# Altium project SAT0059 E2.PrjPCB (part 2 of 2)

## Sheet MCU.SchDoc: MCU
size 431 x 279 mm; Date: Not shown in title block; ApprovedBy: Not shown in title block; CheckedBy: Not shown in title block; Author: Not shown in title block; CompanyName: Not shown in title block; DrawnBy: B. Shaffer; Engineer: Not shown in title block; Organization: Not shown in title block; Address1: Not shown in title block; Address2: Not shown in title block; Address3: Not shown in title block; Address4: Not shown in title block; DocumentNumber: 6; Revision: Use project parameter SCH_Rev; SheetNumber: 6; SheetTotal: 8; PageSetup: Record=PageOptions|CenterHorizontal=True|CenterVertical=True|PrintScale=0.96|XCorrection=1.00|YCorrection=1.00|PrintKind=0|BorderSize=5000000|LeftOffset=0|BottomOffset=0|Orientation=2|PaperLength=1000|PaperWidth=1000|Scale=100|PaperSource=15|PrintQuality=600|MediaType=1|DitherType=10|PaperKind=11x17|PrintScaleMode=1
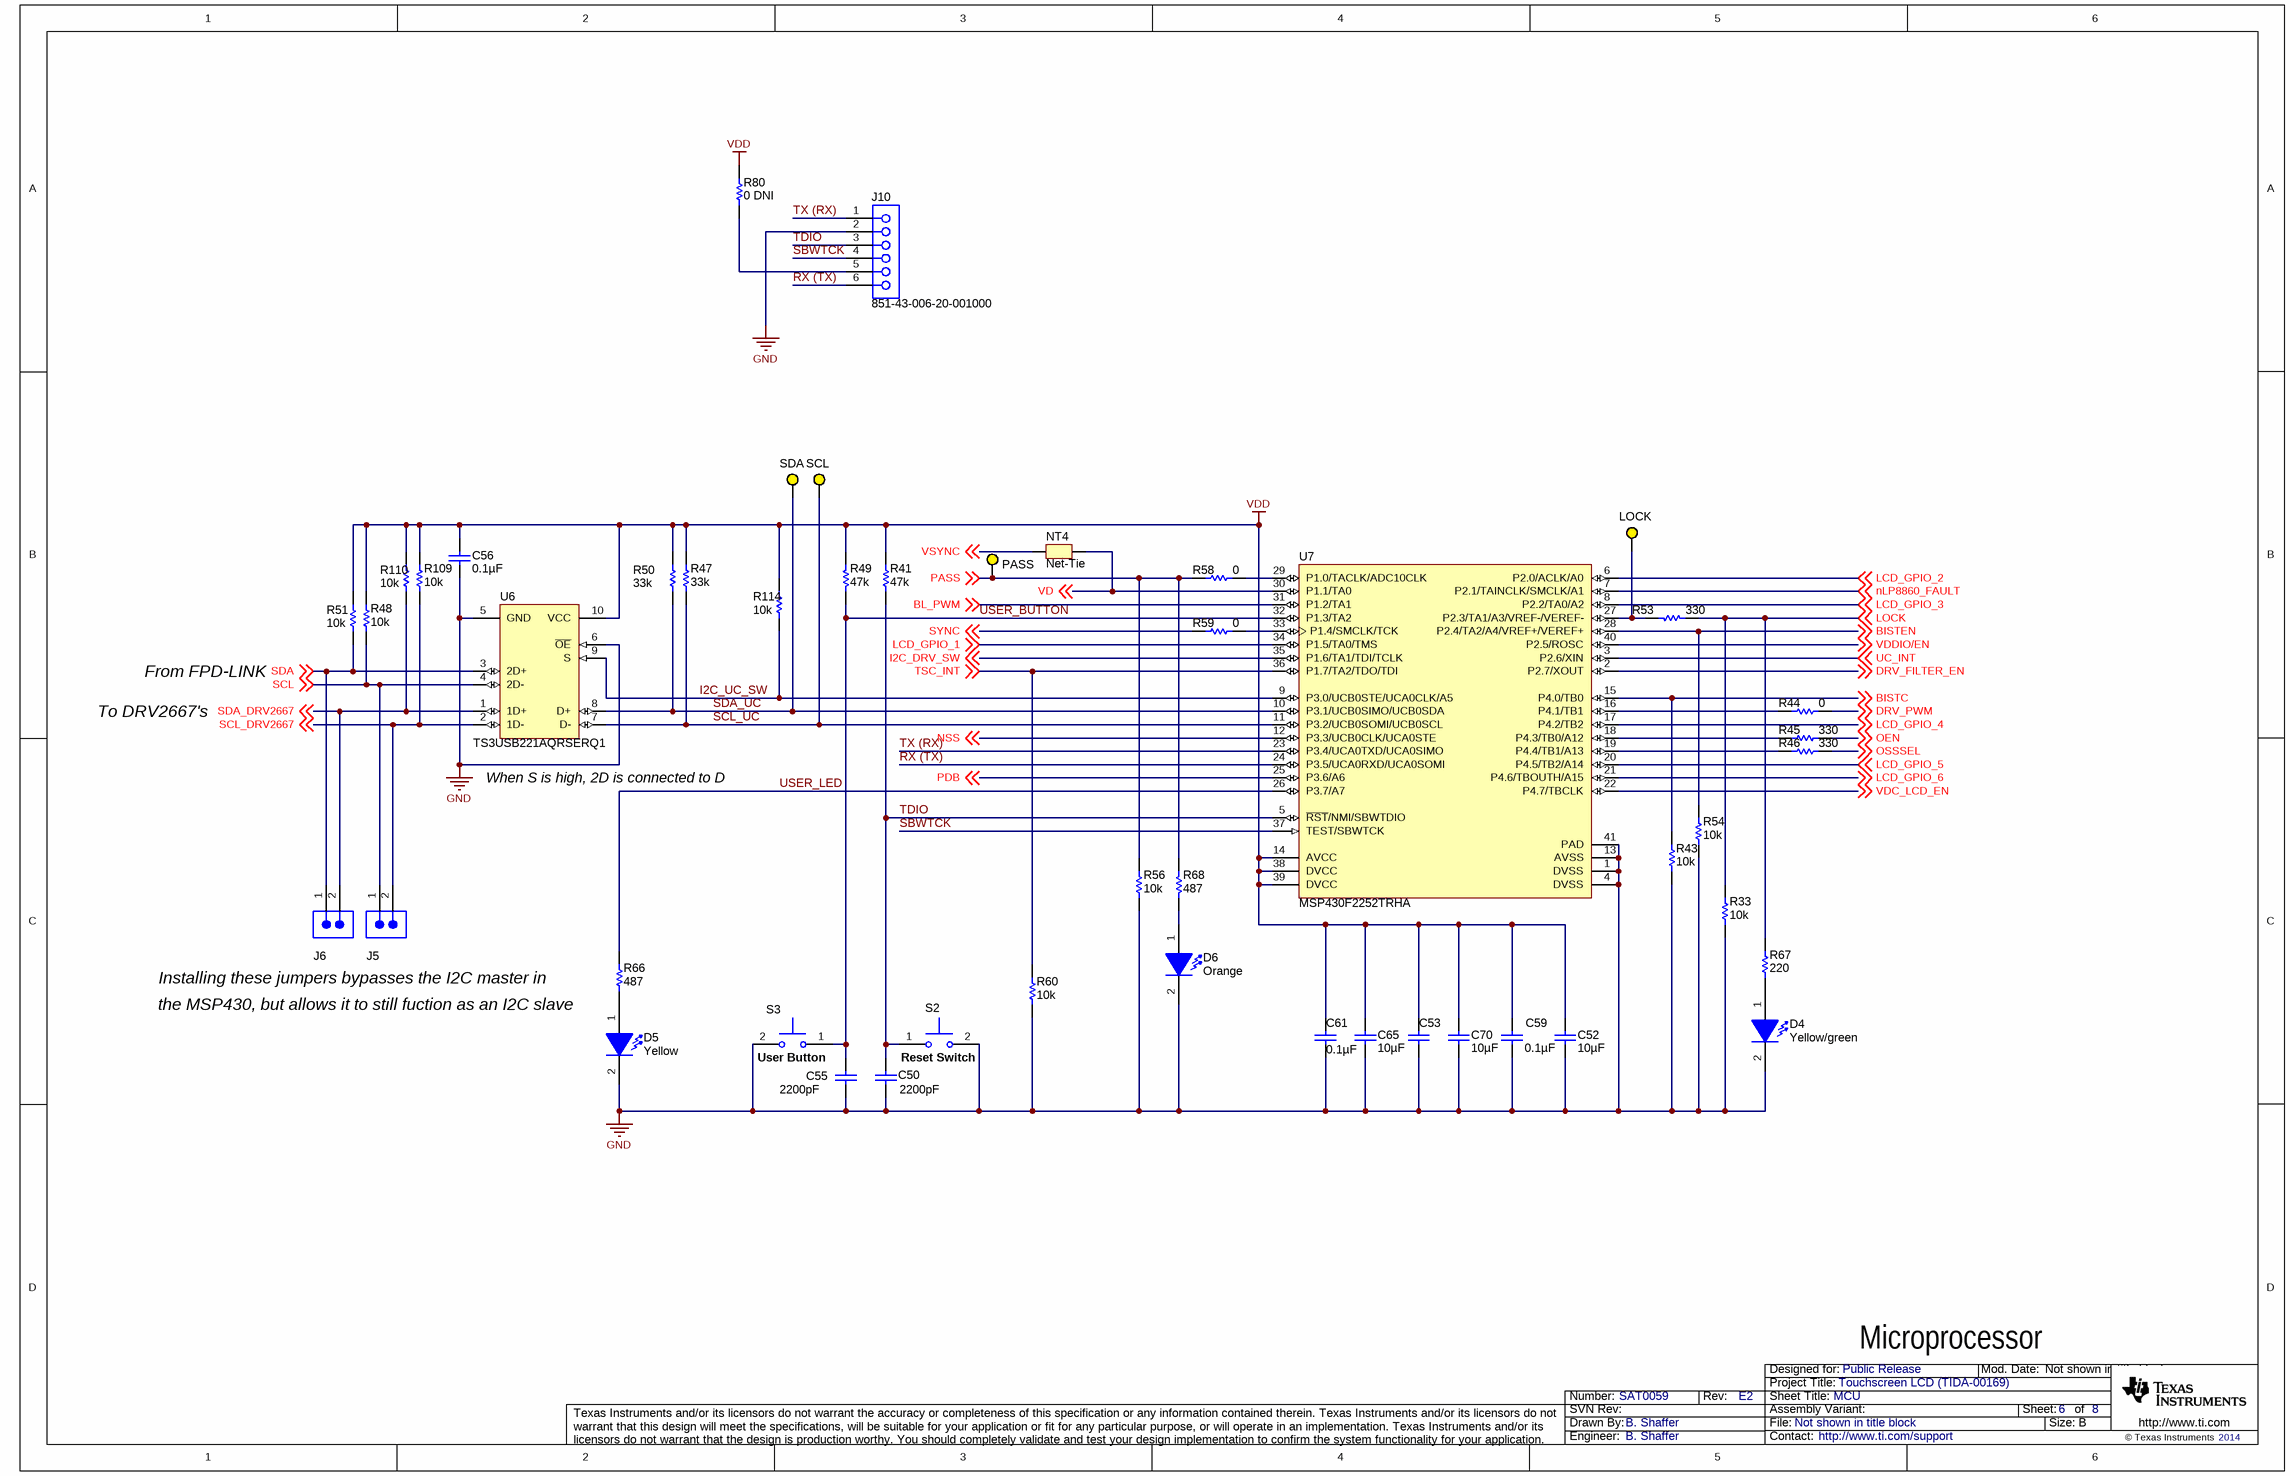
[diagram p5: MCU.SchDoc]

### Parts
C50  value 2200pF  [0402]  (hidden comment: UMK105B7222KV-F)
C52  ValueDisplayed: 10µF  [0805_HV]  (hidden comment: GRM21BR71A106KE51L)
C53  C1005X5R1A104K  [0402]  (value not drawn)
C55  value 2200pF  [0402]  (hidden comment: UMK105B7222KV-F)
C56  ValueDisplayed: 0.1µF  [0603]  (hidden comment: 0603YC104JAT2A)
C59  ValueDisplayed: 0.1µF  [0402]  (hidden comment: C1005X5R1A104K)
C61  ValueDisplayed: 0.1µF  [0402]  (hidden comment: C1005X5R1A104K)
C65  ValueDisplayed: 10µF  [0805_HV]  (hidden comment: GRM21BR71A106KE51L)
C70  ValueDisplayed: 10µF  [0805_HV]  (hidden comment: GRM21BR71A106KE51L)
D4  value Yellow/green  [SML-P1_YELLOW-GREEN]  (hidden comment: SML-P12MTT86)
D5  value Yellow  [LED_SMLP12_Yellow]  (hidden comment: SML-P12YTT86)
D6  value Orange  [LED_SMLP12_ORANGE]  (hidden comment: SML-P12DTT86)
J5  TSW-102-07-G-S  [TSW-102-07-G-S]  (value not drawn)
J6  TSW-102-07-G-S  [TSW-102-07-G-S]  (value not drawn)
J10  851-43-006-20-001000  [CONN_851-43-006-20-001000]
LOCK  5004  [Keystone5004]  (value not drawn)
NT4  Net-Tie  [Net-Tie_10mil]  (net tie, no BOM)
PASS  5004  [Keystone5004]  (value not drawn)
R33  value 10k  [0402]  (hidden comment: CRCW040210K0JNED)
R41  value 47k  [0402]  (hidden comment: CRCW040247K0JNED)
R43  value 10k  [0402]  (hidden comment: CRCW040210K0JNED)
R44  value 0  [0603]  (hidden comment: CRCW06030000Z0EA)
R45  value 330  [0402]  (hidden comment: CRCW0402330RJNED)
R46  value 330  [0402]  (hidden comment: CRCW0402330RJNED)
R47  value 33k  [0402]  (hidden comment: CRCW040233K0JNED)
R48  value 10k  [0402]  (hidden comment: CRCW040210K0JNED)
R49  value 47k  [0402]  (hidden comment: CRCW040247K0JNED)
R50  value 33k  [0402]  (hidden comment: CRCW040233K0JNED)
R51  value 10k  [0402]  (hidden comment: CRCW040210K0JNED)
R53  value 330  [0402]  (hidden comment: CRCW0402330RJNED)
R54  value 10k  [0402]  (hidden comment: CRCW040210K0JNED)
R56  value 10k  [0402]  (hidden comment: CRCW040210K0JNED)
R58  value 0  [0603]  (hidden comment: CRCW06030000Z0EA)
R59  value 0  [0603]  (hidden comment: CRCW06030000Z0EA)
R60  value 10k  [0402]  (hidden comment: CRCW040210K0JNED)
R66  value 487  [0402]  (hidden comment: CRCW0402487RFKED)
R67  value 220  [0402]  (hidden comment: CRCW0402220RJNED)
R68  value 487  [0402]  (hidden comment: CRCW0402487RFKED)
R80  value 0 DNI  [0603]  (hidden comment: CRCW06030000Z0EA)
R109  value 10k  [0402]  (hidden comment: CRCW040210K0JNED)
R110  value 10k  [0402]  (hidden comment: CRCW040210K0JNED)
R114  value 10k  [0603]  (hidden comment: CRCW060310K0JNEA)
S2  SKRKAEE010  [SW_SKRKAEE010]  (value not drawn)
S3  SKRKAEE010  [SW_SKRKAEE010]  (value not drawn)
SCL  5004  [Keystone5004]  (value not drawn)
SDA  5004  [Keystone5004]  (value not drawn)
U6  TS3USB221AQRSERQ1  [RSE0010A]
U7  MSP430F2252TRHA  [RHA0040B]

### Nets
GND: C50.2 C52.2 C53.2 C55.2 C56.2 C59.2 C61.2 C65.2 C70.2 D4.2(K) D5.2(K) D6.2(K) J10.2 R33.1 R43.1 R54.1 R56.1 R60.1 S2.2 S3.2 U6.5(GND) U6.6(~{OE}) U7.1(DVSS) U7.4(DVSS) U7.13(AVSS) U7.41(PAD)
VDD: C52.1 C53.1 C56.1 C59.1 C61.1 C65.1 C70.1 R41.2 R47.2 R48.2 R49.2 R50.2 R51.2 R80.2 R109.2 R110.2 R114.1 U6.10(VCC) U7.14(AVCC) U7.38(DVCC) U7.39(DVCC)
BISTC: R43.2 U7.15(P4.0/TB0) ; off-sheet BISTC
BISTEN: R54.2 U7.28(P2.4/TA2/A4/VREF+/VEREF+) ; off-sheet BISTEN
BL_PWM: U7.31(P1.2/TA1) ; off-sheet BL_PWM
DRV_FILTER_EN: U7.2(P2.7/XOUT) ; off-sheet DRV_FILTER_EN
DRV_PWM: R44.1 ; off-sheet DRV_PWM
I2C_DRV_SW: U7.35(P1.6/TA1/TDI/TCLK) ; off-sheet I2C_DRV_SW
I2C_UC_SW: R114.2 U6.9(S) U7.9(P3.0/UCB0STE/UCA0CLK/A5)
LCD_GPIO_1: U7.34(P1.5/TA0/TMS) ; off-sheet LCD_GPIO_1
LCD_GPIO_2: U7.6(P2.0/ACLK/A0) ; off-sheet LCD_GPIO_2
LCD_GPIO_3: U7.8(P2.2/TA0/A2) ; off-sheet LCD_GPIO_3
LCD_GPIO_4: U7.17(P4.2/TB2) ; off-sheet LCD_GPIO_4
LCD_GPIO_5: U7.20(P4.5/TB2/A14) ; off-sheet LCD_GPIO_5
LCD_GPIO_6: U7.21(P4.6/TBOUTH/A15) ; off-sheet LCD_GPIO_6
LOCK: R33.2 R53.1 R67.2 ; off-sheet LOCK
nLP8860_FAULT: U7.7(P2.1/TAINCLK/SMCLK/A1) ; off-sheet nLP8860_FAULT
NSS: U7.12(P3.3/UCB0CLK/UCA0STE) ; off-sheet NSS
OEN: R45.2 ; off-sheet OEN
OSSSEL: R46.2 ; off-sheet OSSSEL
PASS: PASS.1 R56.2 R58.2 R68.2 ; off-sheet PASS
PDB: U7.25(P3.6/A6) ; off-sheet PDB
RX (TX): J10.6 U7.24(P3.5/UCA0RXD/UCA0SOMI)
SBWTCK: J10.4 U7.37(TEST/SBWTCK)
SCL: J5.1 R48.1 U6.4(2D-) ; off-sheet SCL
SCL_DRV2667: J5.2 R109.1 U6.2(1D-) ; off-sheet SCL_DRV2667
SCL_UC: R47.1 SCL.1 U6.7(D-) U7.11(P3.2/UCB0SOMI/UCB0SCL)
SDA: J6.1 R51.1 U6.3(2D+) ; off-sheet SDA
SDA_DRV2667: J6.2 R110.1 U6.1(1D+) ; off-sheet SDA_DRV2667
SDA_UC: R50.1 SDA.1 U6.8(D+) U7.10(P3.1/UCB0SIMO/UCB0SDA)
SYNC: R59.2 ; off-sheet SYNC
TDIO: C50.1 J10.3 R41.1 S2.1 U7.5(~{RST}/NMI/SBWTDIO)
TSC_INT: R60.2 U7.36(P1.7/TA2/TDO/TDI) ; off-sheet TSC_INT
TX (RX): J10.1 U7.23(P3.4/UCA0TXD/UCA0SIMO)
UC_INT: U7.3(P2.6/XIN) ; off-sheet UC_INT
USER_BUTTON: C55.1 R49.1 S3.1 U7.32(P1.3/TA2)
USER_LED: R66.2 U7.26(P3.7/A7)
VD: NT4.2 U7.30(P1.1/TA0) ; off-sheet VD
VDC_LCD_EN: U7.22(P4.7/TBCLK) ; off-sheet VDC_LCD_EN
VDDIO/EN: U7.40(P2.5/ROSC) ; off-sheet VDDIO/EN
VSYNC: NT4.1 ; off-sheet VSYNC
NetD4_1: D4.1(A) R67.1
NetD5_1: D5.1(A) R66.1
NetD6_1: D6.1(A) R68.1
NetJ10_5: J10.5 R80.1
NetLOCK_1: LOCK.1 R53.2 U7.27(P2.3/TA1/A3/VREF-/VEREF-)
NetR44_2: R44.2 U7.16(P4.1/TB1)
NetR45_1: R45.1 U7.18(P4.3/TB0/A12)
NetR46_1: R46.1 U7.19(P4.4/TB1/A13)
NetR58_1: R58.1 U7.29(P1.0/TACLK/ADC10CLK)
NetR59_1: R59.1 U7.33(P1.4/SMCLK/TCK)

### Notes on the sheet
- From FPD-LINK
- To DRV2667's
- (near U6) When S is high, 2D is connected to D
- Installing these jumpers bypasses the I2C master in
- (near R66) the MSP430, but allows it to still fuction as an I2C slave
- (near S3) User Button
- (near S2) Reset Switch
- Microprocessor

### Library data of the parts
C50 C55 = Capacitor: CAP CER 2200PF 50V 10% X7R 0402; Manufacturer: Taiyo Yuden; Polarized: N; U/M: EA
C52 C65 C70 = GRM21BR71A106KE51L: CAP, CERM, 10uF, 10V, +/-10%, X7R, 0805; Manufacturer: MuRata; Polarized: N; CompType: Capacitor; U/M: EA; Cap_F: 0.00001; Tolerance_%: 10; ESR_Ohm: 0.003; Value1: 0.003 ohm; TaMin_C: -55; TaMax_C: 125; Cap_Case: 0805
C53 C59 C61 = C1005X5R1A104K: CAP, CERM, 0.1uF, 10V, +/-10%, X5R, 0402; Manufacturer: TDK; Polarized: N; CompType: Capacitor; U/M: EA; Cap_F: 0.0000001; Tolerance_%: 10; ESR_Ohm: 0.0186; Value1: 0.0186 ohm; TaMin_C: -55; TaMax_C: 85
C56 = 0603YC104JAT2A: CAP, CERM, 0.1uF, 16V, +/-5%, X7R, 0603; Manufacturer: AVX; Polarized: N; CompType: Capacitor; U/M: EA; Cap_F: 0.0000001; Tolerance_%: 5; ESR_Ohm: 0.039; Value1: 0.039 ohm; VDC_V: 16; TaMin_C: -55; TaMax_C: 125
D4 = SML-P12MTT86: LED, Yellow/green, SMD; Manufacturer: Rohm; Type: AlInGaP; Vf_V: 2.2; Value2: 2.2V; Io_A: 0.02; Value1: W; U/M: EA
D5 = SML-P12YTT86: LED, Yellow, SMD; Manufacturer: Rohm; Type: InGaN; Vf_V: 2.1; Value2: 2.1V; Io_A: 0.02; Tjmax_C: 85; Value1: W; U/M: EA
D6 = SML-P12DTT86: LED, Orange, SMD; Manufacturer: Rohm; Type: InGaN; Vf_V: 2.1; Value2: 2.1V; Io_A: 0.02; Tjmax_C: 85; Value1: W; U/M: EA
J5 J6 = TSW-102-07-G-S: Header, TH, 100mil, 2x1, Gold plated, 230 mil above insulator; Manufacturer: Samtec, Inc.; U/M: EA
J10 = 851-43-006-20-001000: Receptacle, 50mil, 6x1, R/A, TH; Manufacturer: Mill-Max; SymbolCreator: a0411947; U/M: EA
LOCK PASS SCL SDA = 5004: Test Point, Miniature, Yellow, TH; Manufacturer: Keystone; CompType: Test Point Loop; U/M: EA
NT4 = Net-Tie: Single point connection between nets.; SymbolCreator: codlsc
R33 R43 R48 R51 R54 R56 R60 R109 R110 = CRCW040210K0JNED: RES, 10k ohm, 5%, 0.063W, 0402; Manufacturer: Vishay-Dale; CompType: Resistor; Res_ohm: 10000; Value_Code: 10k0; Tolerance_%: 5; Power_W: 0.063; VDC_V: 50; TempCo: 200 ppm/C; EIA_Code: E24; U/M: EA
R41 R49 = CRCW040247K0JNED: RES, 47k ohm, 5%, 0.063W, 0402; Manufacturer: Vishay-Dale; Alternate Manufacturer: Any; Alternate PartNumber: Equivalent; CompType: Resistor; Res_ohm: 47000; Value_Code: 47k0; Tolerance_%: 5; Power_W: 0.063; VDC_V: 50; TempCo: 200 ppm/C; EIA_Code: E24; U/M: EA
R44 R58 R59 = CRCW06030000Z0EA: RES, 0 ohm, 5%, 0.1W, 0603; Manufacturer: Vishay-Dale; CompType: Resistor; Value_Code: 0000; Tolerance_%: 5; Power_W: 0.1; VDC_V: 75; TempCo: 200 ppm/C; EIA_Code: E24; U/M: EA
R45 R46 R53 = CRCW0402330RJNED: RES, 330 ohm, 5%, 0.063W, 0402; Manufacturer: Vishay-Dale; CompType: Resistor; Value_Code: 330R; Tolerance_%: 5; Power_W: 0.063; VDC_V: 50; TempCo: 200 ppm/C; EIA_Code: E24; U/M: EA
R47 R50 = CRCW040233K0JNED: RES, 33k ohm, 5%, 0.063W, 0402; Manufacturer: Vishay-Dale; CompType: Resistor; Res_ohm: 33000; Value_Code: 33k0; Tolerance_%: 5; Power_W: 0.063; VDC_V: 50; TempCo: 200 ppm/C; EIA_Code: E24; U/M: EA
R66 R68 = CRCW0402487RFKED: RES, 487 ohm, 1%, 0.063W, 0402; Manufacturer: Vishay-Dale; Alternate Manufacturer: Any; Alternate PartNumber: Equivalent; CompType: Resistor; Value_Code: 487R; Tolerance_%: 1; Power_W: 0.063; VDC_V: 50; TempCo: 100 ppm/C; EIA_Code: E96; U/M: EA
R67 = CRCW0402220RJNED: RES, 220 ohm, 5%, 0.063W, 0402; Manufacturer: Vishay-Dale; Alternate Manufacturer: Any; Alternate PartNumber: Equivalent; CompType: Resistor; Value_Code: 220R; Tolerance_%: 5; Power_W: 0.063; VDC_V: 50; TempCo: 200 ppm/C; EIA_Code: E24; U/M: EA
R80 = CRCW06030000Z0EA: RES, 0 ohm, 5%, 0.1W, 0603; Manufacturer: Vishay-Dale; CompType: Resistor; Res_ohm: 0; Value_Code: 0000; Tolerance_%: 5; Power_W: 0.1; VDC_V: 75; TempCo: 200 ppm/C; EIA_Code: E24; U/M: EA
R114 = CRCW060310K0JNEA: RES, 10k ohm, 5%, 0.1W, 0603; Manufacturer: Vishay-Dale; CompType: Resistor; Res_ohm: 10000; Value_Code: 10k0; Tolerance_%: 5; Power_W: 0.1; VDC_V: 75; TempCo: 200 ppm/C; EIA_Code: E24; U/M: EA
S2 S3 = SKRKAEE010: Switch, Push Button, SMD; Manufacturer: Alps; Alternate Manufacturer: Any; Alternate PartNumber: Equivalent; SymbolCreator: a0412235; Circuit: SPST-NO; VDC_V: 12; SwitchFunction: Off-Mom; PositionCount: 1; CurrentRating_mA: 50
U6 = TS3USB221AQRSERQ1: Automotive Catalog ESD Protected, High-Speed USB 2.0 (480-Mbps) 1:2 Multiplexer / Demultiplexer Switch, 16 ohm RON, 2.5 to 3.3V, -40 to 125 degC, 10-Pin UQFN (RSE), Green (RoHS & no Sb/Br); Manufacturer: Texas Instruments; Alternate Manufacturer: None; Alternate PartNumber: Equivalent; SubFamily: USB Switch; Number of Channels: 2; Architecture: 1; ESD HBM(kV): +/-7; ICC(uA): 30; tpd max(ns): 0.25; ron(max)(ohms): 16; RON Mis-match(Max)(Ohms): 0.2; Bandwidth(MHz): 900; ON Time(Max)(ns): 12
U7 = MSP430F2252TRHA: Mixed Signal MicroController, RHA0040B; Alternate Manufacturer: None; Manufacturer: Texas Instruments; ADC: 10-bit SAR; ADC Channels: 12; Brown Out Reset: Yes; Eco-Plan: TBD; Flash(KB): 16; GPIO: 32; SRAM(B): 512; Timers - 16-bit: 2; USCI_A (UART/LIN/IrDA/SPI): 1; SymbolCreator: Altium/a0412235; CompType: IC; U/M: EA

## Sheet Connectors.SchDoc: Connectors
size 431 x 279 mm; Date: Not shown in title block; ApprovedBy: Not shown in title block; CheckedBy: Not shown in title block; Author: Not shown in title block; CompanyName: Not shown in title block; DrawnBy: B. Shaffer; Engineer: Not shown in title block; Organization: Not shown in title block; Address1: Not shown in title block; Address2: Not shown in title block; Address3: Not shown in title block; Address4: Not shown in title block; DocumentNumber: 7; Revision: Use project parameter SCH_Rev; SheetNumber: 7; SheetTotal: 8; PageSetup: Record=PageOptions|CenterHorizontal=True|CenterVertical=True|PrintScale=0.96|XCorrection=1.00|YCorrection=1.00|PrintKind=0|BorderSize=5000000|LeftOffset=0|BottomOffset=0|Orientation=2|PaperLength=1000|PaperWidth=1000|Scale=100|PaperSource=15|PrintQuality=600|MediaType=1|DitherType=10|PaperKind=Tabloid (11 x 17")|PrintScaleMode=1
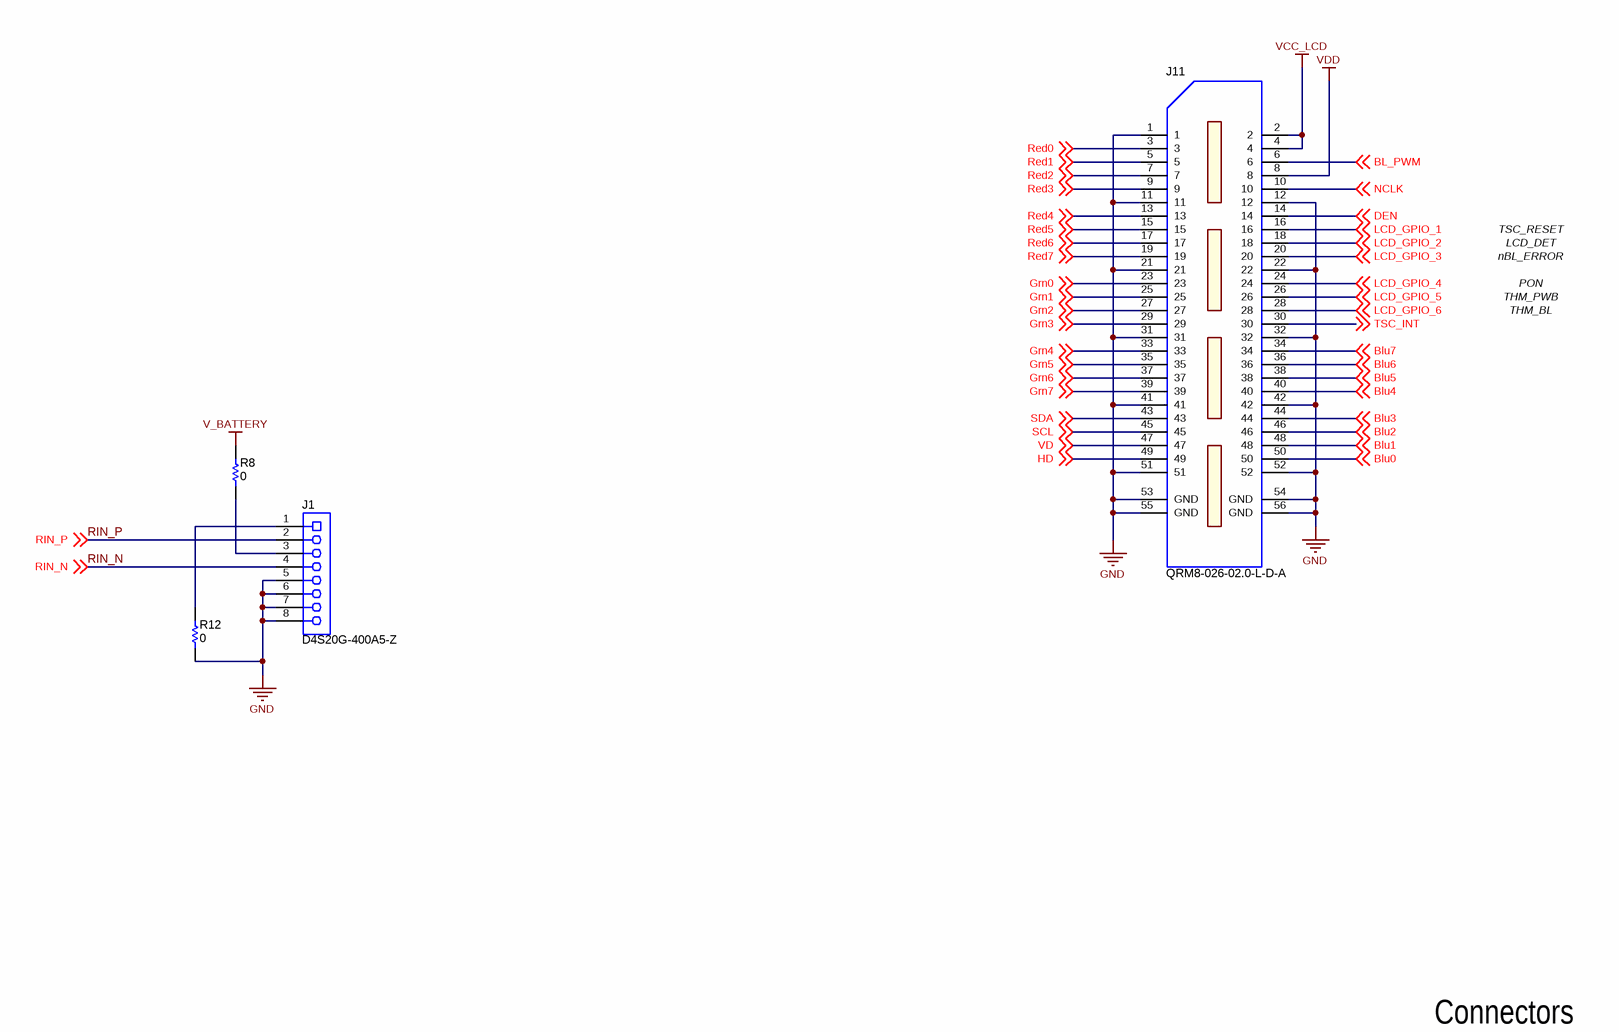
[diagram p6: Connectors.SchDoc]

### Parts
J1  D4S20G-400A5-Z  [Rosenberger_D4S20G-400A5]
J11  QRM8-026-02.0-L-D-A  [Samtec_QRM8-026-02.0-L-D-A]
R8  value 0  [0603]  (hidden comment: CRCW06030000Z0EA)
R12  value 0  [0603]  (hidden comment: CRCW06030000Z0EA)

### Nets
GND: J1.5 J1.6 J1.7 J1.8 J11.1 J11.11 J11.12 J11.21 J11.22 J11.31 J11.32 J11.41 J11.42 J11.51 J11.52 J11.53(GND) J11.54(GND) J11.55(GND) J11.56(GND) R12.1
V_BATTERY: R8.2
VCC_LCD: J11.2 J11.4
VDD: J11.8
BL_PWM: J11.6 ; off-sheet BL_PWM
Blu0: J11.50 ; off-sheet Blu0
Blu1: J11.48 ; off-sheet Blu1
Blu2: J11.46 ; off-sheet Blu2
Blu3: J11.44 ; off-sheet Blu3
Blu4: J11.40 ; off-sheet Blu4
Blu5: J11.38 ; off-sheet Blu5
Blu6: J11.36 ; off-sheet Blu6
Blu7: J11.34 ; off-sheet Blu7
DEN: J11.14 ; off-sheet DEN
Grn0: J11.23 ; off-sheet Grn0
Grn1: J11.25 ; off-sheet Grn1
Grn2: J11.27 ; off-sheet Grn2
Grn3: J11.29 ; off-sheet Grn3
Grn4: J11.33 ; off-sheet Grn4
Grn5: J11.35 ; off-sheet Grn5
Grn6: J11.37 ; off-sheet Grn6
Grn7: J11.39 ; off-sheet Grn7
HD: J11.49 ; off-sheet HD
LCD_GPIO_1: J11.16 ; off-sheet LCD_GPIO_1
LCD_GPIO_2: J11.18 ; off-sheet LCD_GPIO_2
LCD_GPIO_3: J11.20 ; off-sheet LCD_GPIO_3
LCD_GPIO_4: J11.24 ; off-sheet LCD_GPIO_4
LCD_GPIO_5: J11.26 ; off-sheet LCD_GPIO_5
LCD_GPIO_6: J11.28 ; off-sheet LCD_GPIO_6
NCLK: J11.10 ; off-sheet NCLK
Red0: J11.3 ; off-sheet Red0
Red1: J11.5 ; off-sheet Red1
Red2: J11.7 ; off-sheet Red2
Red3: J11.9 ; off-sheet Red3
Red4: J11.13 ; off-sheet Red4
Red5: J11.15 ; off-sheet Red5
Red6: J11.17 ; off-sheet Red6
Red7: J11.19 ; off-sheet Red7
RIN_N: J1.4 ; off-sheet RIN_N
RIN_P: J1.2 ; off-sheet RIN_P
SCL: J11.45 ; off-sheet SCL
SDA: J11.43 ; off-sheet SDA
TSC_INT: J11.30 ; off-sheet TSC_INT
VD: J11.47 ; off-sheet VD
NetJ1_1: J1.1 R12.2
NetJ1_3: J1.3 R8.1

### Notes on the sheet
- TSC_RESET
- LCD_DET
- nBL_ERROR
- PON
- THM_PWB
- THM_BL
- Connectors

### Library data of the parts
J1 = D4S20G-400A5-Z: RIGHT ANGLE PLUG FOR PCB; Manufacturer: Rosenberger; SymbolCreator: a0411947; U/M: EA
J11 = QRM8-026-02.0-L-D-A: Slim body GND plane Socket 2x26, 2mm body height, Ag on contact, Alignment, SMD; Manufacturer: Samtec; CompType: Connector; U/M: EA
R8 R12 = CRCW06030000Z0EA: as R44 on sheet MCU

## Sheet Hardware.SchDoc: Hardware
size 431 x 279 mm; Date: Not shown in title block; ApprovedBy: Not shown in title block; CheckedBy: Not shown in title block; Author: Not shown in title block; CompanyName: Not shown in title block; DrawnBy: B. Shaffer; Engineer: Not shown in title block; Organization: Not shown in title block; Address1: Not shown in title block; Address2: Not shown in title block; Address3: Not shown in title block; Address4: Not shown in title block; DocumentNumber: 8; Revision: Use project parameter SCH_Rev; SheetNumber: 8; SheetTotal: 8; PageSetup: Record=PageOptions|CenterHorizontal=True|CenterVertical=True|PrintScale=1.00|XCorrection=1.00|YCorrection=1.00|PrintKind=0|BorderSize=5000000|LeftOffset=0|BottomOffset=0|Orientation=2|PaperLength=1000|PaperWidth=1000|Scale=100|PaperSource=15|PrintQuality=600|MediaType=1|DitherType=10|PaperKind=Letter|PrintScaleMode=1
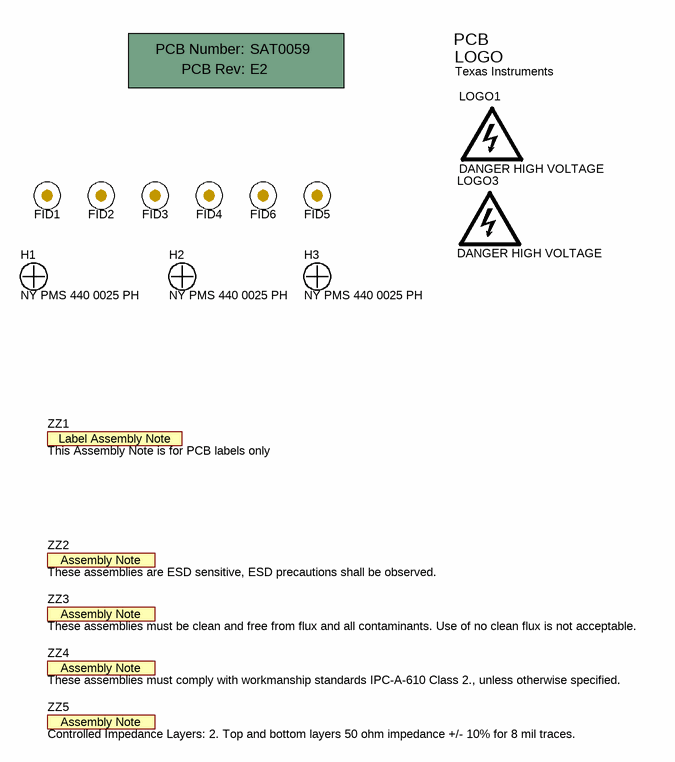
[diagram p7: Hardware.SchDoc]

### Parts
!PCB1  Printed Circuit Board  (value not drawn)  (mechanical)
FID1  Fiducial  [Fiducial10-20]  (value not drawn)
FID2  Fiducial  [Fiducial10-20]  (value not drawn)
FID3  Fiducial  [Fiducial10-20]  (value not drawn)
FID4  Fiducial  [Fiducial10-20]  (value not drawn)
FID5  Fiducial  [Fiducial10-20]  (value not drawn)
FID6  Fiducial  [Fiducial10-20]  (value not drawn)
H1  NY PMS 440 0025 PH  [NY PMS 440 0025 PH]
H2  NY PMS 440 0025 PH  [NY PMS 440 0025 PH]
H3  NY PMS 440 0025 PH  [NY PMS 440 0025 PH]
LOGO1  DANGER HIGH VOLTAGE  [IEC_HighVoltage_Small]  (no BOM)
Logo2  Texas Instruments  [TI_Horizontal_Overlay_Small]  (no BOM)
LOGO3  DANGER HIGH VOLTAGE  [IEC_HighVoltage_Small]  (no BOM)
ZZ1  This Assembly Note is for PCB labels only  [AssemblyNoteLabel]  (no BOM)
ZZ2  These assemblies are ESD sensitive, ESD precautions shall be observed.  [AssemblyNote]  (no BOM)
ZZ3  These assemblies must be clean and free from flux and all contaminants. Use of no clean flux is not acceptable.  [AssemblyNote]  (no BOM)
ZZ4  These assemblies must comply with workmanship standards IPC-A-610 Class 2., unless otherwise specified.  [AssemblyNote]  (no BOM)
ZZ5  Controlled Impedance Layers: 2. Top and bottom layers 50 ohm impedance +/- 10% for 8 mil traces.  [AssemblyNote]  (no BOM)

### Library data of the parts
!PCB1 = PCB: Manufacturer: Any; PartNumber: SAT0059; SymbolCreator: a0412235
FID1-FID6 = Fiducial: Fiducial mark.  There is nothing to buy or mount.; SymbolCreator: codlsc
H1-H3 = NY PMS 440 0025 PH: Machine Screw, Round, #4-40 x 1/4, Nylon, Philips panhead; Manufacturer: B&F Fastener Supply; CompType: Hardware; SymbolCreator: codlsc; U/M: EA
LOGO1 LOGO3 = IEC_HighVoltage: IEC 61010-1 High Voltage Warning; SymbolCreator: a0412235
Logo2 = TI_Logo: Texas Instrument Corporate Signature; SymbolCreator: codlsc
ZZ1 = AssemblyNoteLabel: SymbolCreator: a0412235
ZZ2-ZZ5 = AssemblyNote: SymbolCreator: codlsc

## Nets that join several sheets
GND: Power Supplies (20 pins), Deserializer (26 pins), LED Driver (32 pins), Haptic Drivers (44 pins), MCU (26 pins), Connectors (20 pins)
V_BATTERY: Power Supplies (D1.2 J3.1), Connectors (R8.2)
VCC_LCD: Power Supplies (D8.2 TP3.1 U5.7 U5.8), Connectors (J11.2 J11.4)
VDD: Power Supplies (8 pins), Deserializer (5 pins), LED Driver (C76.2 R78.1 R81.1 U9.3), Haptic Drivers (18 pins), MCU (21 pins), Connectors (J11.8)
VIN: Power Supplies (5 pins), LED Driver (R112.2)
BISTC: Deserializer (U3.16), MCU (R43.2 U7.15)
BISTEN: Deserializer (U3.44), MCU (R54.2 U7.28)
BL_PWM: LED Driver (U9.18), MCU (U7.31), Connectors (J11.6)
Blu0: Deserializer (R86.2), Connectors (J11.50)
Blu1: Deserializer (R87.2), Connectors (J11.48)
Blu2: Deserializer (R88.2), Connectors (J11.46)
Blu3: Deserializer (R95.2), Connectors (J11.44)
Blu4: Deserializer (R96.2), Connectors (J11.40)
Blu5: Deserializer (R97.2), Connectors (J11.38)
Blu6: Deserializer (R98.2), Connectors (J11.36)
Blu7: Deserializer (R99.2), Connectors (J11.34)
DEN: Deserializer (U3.6), Connectors (J11.14)
DRV_FILTER_EN: Haptic Drivers (R7.2 R71.2), MCU (U7.2)
DRV_PWM: Haptic Drivers (R18.1 R63.1), MCU (R44.1)
Grn0: Deserializer (R89.2), Connectors (J11.23)
Grn1: Deserializer (R90.2), Connectors (J11.25)
Grn2: Deserializer (R91.2), Connectors (J11.27)
Grn3: Deserializer (R92.2), Connectors (J11.29)
Grn4: Deserializer (R93.2), Connectors (J11.33)
Grn5: Deserializer (R83.2), Connectors (J11.35)
Grn6: Deserializer (R84.2), Connectors (J11.37)
Grn7: Deserializer (R85.2), Connectors (J11.39)
HD: Deserializer (U3.8), Connectors (J11.49)
I2C_DRV_SW: Deserializer (R34.1), Haptic Drivers (R113.1 U4.9), MCU (U7.35)
LCD_GPIO_1: MCU (U7.34), Connectors (J11.16)
LCD_GPIO_2: MCU (U7.6), Connectors (J11.18)
LCD_GPIO_3: MCU (U7.8), Connectors (J11.20)
LCD_GPIO_4: MCU (U7.17), Connectors (J11.24)
LCD_GPIO_5: MCU (U7.20), Connectors (J11.26)
LCD_GPIO_6: MCU (U7.21), Connectors (J11.28)
LOCK: Deserializer (U3.32), MCU (R33.2 R53.1 R67.2)
NCLK: Deserializer (U3.5), Connectors (J11.10)
nLP8860_FAULT: LED Driver (R81.2 U9.11), MCU (U7.7)
NSS: LED Driver (U9.17), MCU (U7.12)
OEN: Deserializer (R42.2 U3.31), MCU (R45.2)
OSSSEL: Deserializer (U3.46), MCU (R46.2)
PASS: Deserializer (U3.42), MCU (PASS.1 R56.2 R58.2 R68.2)
PDB: Deserializer (R19.2 U3.59), MCU (U7.25)
Red0: Deserializer (R106.2), Connectors (J11.3)
Red1: Deserializer (R105.2), Connectors (J11.5)
Red2: Deserializer (R104.2), Connectors (J11.7)
Red3: Deserializer (R103.2), Connectors (J11.9)
Red4: Deserializer (R102.2), Connectors (J11.13)
Red5: Deserializer (R101.2), Connectors (J11.15)
Red6: Deserializer (R100.2), Connectors (J11.17)
Red7: Deserializer (R94.2), Connectors (J11.19)
RIN_N: Deserializer (L3.1), Connectors (J1.4)
RIN_P: Deserializer (L3.4), Connectors (J1.2)
SCL: Deserializer (U3.3), LED Driver (U9.16), MCU (J5.1 R48.1 U6.4), Connectors (J11.45)
SCL_DRV2667: Haptic Drivers (U4.7), MCU (J5.2 R109.1 U6.2)
SDA: Deserializer (U3.2), LED Driver (U9.15), MCU (J6.1 R51.1 U6.3), Connectors (J11.43)
SDA_DRV2667: Haptic Drivers (U4.8), MCU (J6.2 R110.1 U6.1)
SYNC: LED Driver (U9.12), MCU (R59.2)
TSC_INT: Deserializer (R23.1), MCU (R60.2 U7.36), Connectors (J11.30)
UC_INT: Deserializer (R24.1), MCU (U7.3)
VD: Deserializer (U3.7), MCU (NT4.2 U7.30), Connectors (J11.47)
VDC_LCD_EN: Power Supplies (R111.1 U5.3), MCU (U7.22)
VDDIO/EN: LED Driver (U9.19), MCU (U7.40)
VSYNC: LED Driver (U9.13), MCU (NT4.1)

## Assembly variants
001: not fitted C14 C30 C31 C41 C49 C51 FID1 FID2 FID3 FID4 FID5 FID6 R8 R12 R32 R78 R80 TP2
